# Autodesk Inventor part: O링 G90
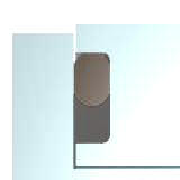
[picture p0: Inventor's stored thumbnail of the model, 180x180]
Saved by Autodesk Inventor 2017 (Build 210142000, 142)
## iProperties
IsCustomPart: 1
Created: 2012-02
Part Number: O링 G90
Material: 고무
Description: O-링
Document SubType Name: Modeling
Standard: JIS B 2406
Designer: mdu-01
Standards Organization: JIS
Language: ko-KR
Size Designation: G 90
Categories: <MemberInstance><Categories><Category DisplayName="샤프트 부품" InternalName="7f7aeb1f-a693-4053-b835-cee3144e0d98" Mnemonic="SHFT"><Category DisplayName="실링" Intern
Density: 0.93 g/cm^3
Appearance: 고무 - 검은색 - 버전 1.1
Author: mdu-01
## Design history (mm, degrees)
revolve "본체" stored, may be unused: angle "d7" = 90 deg
body "Solid1"
sketch "스케치1"
  geometry: L1 (0, 45.95)-(-1.2, 45.95); L2 (-1.2, 45.95)-(-1.2, 44.4); L3 (0, 44.969)-(0, 45.95); L4 (-1.2, 45.95)-(-1.2, 47.5); L5 (0, 46.931)-(0, 45.95) reference; L6 (-2.4, 46.931)-(-2.4, 45.95); L7 (-2.4, 44.969)-(-2.4, 45.95); L8 (-1.2, 45.95)-(-1.2, 47.5); L9 (0, 17.106)-(0, -2.851) reference; L10 (-2, 0)-(1, 0) reference; L11 (-2.62, 0)-(1.603, 0) reference; A1 r 1.55 centre (-1.2, 45.95) between (-1.2, 44.4) and (0, 44.969); A2 r 1.55 centre (-1.2, 45.95) between (0, 46.931) and (-1.2, 47.5); A3 r 1.55 centre (-1.2, 45.95) between (-1.2, 47.5) and (-2.4, 46.931); A4 r 1.55 centre (-1.2, 45.95) between (-2.4, 44.969) and (-1.2, 44.4)
  constraints: 18 end point, 8 point on circle, 5 symmetric about line, 4 centre point, 2 horizontal, 2 perpendicular, 1 parallel, 1 vertical, 9 other
  dimensions: "d0" = 1.55 radius of A1 (= 0.5 x QDM); "d1" = 1.2 distance between parallel lines of L9 L2 (= 0.5 x NTOR); "d2" = 95 diameter of L4.end L10 (= NDO1)
other parameters: "QDM" = 3.1 [user parameter; used in 1 equation term], "NTOR" = 2.4 [user parameter; used in 1 equation term], "NDO1" = 95 [user parameter; used in 1 equation term], "d3" = 0, "d4" = 0, "d5" = 0, "R2" = 0.2 [user parameter], "SD1" = 89.4 [user parameter], "R1" = 0.7 [user parameter], "NB1" = 4.1 [user parameter]
